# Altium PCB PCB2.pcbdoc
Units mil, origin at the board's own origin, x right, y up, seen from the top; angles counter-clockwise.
Board outline 7175 x 3700.9 mil, 2 copper layers (Top Layer, Bottom Layer); 17 components, 36 nets, 146 pads, 3 vias.
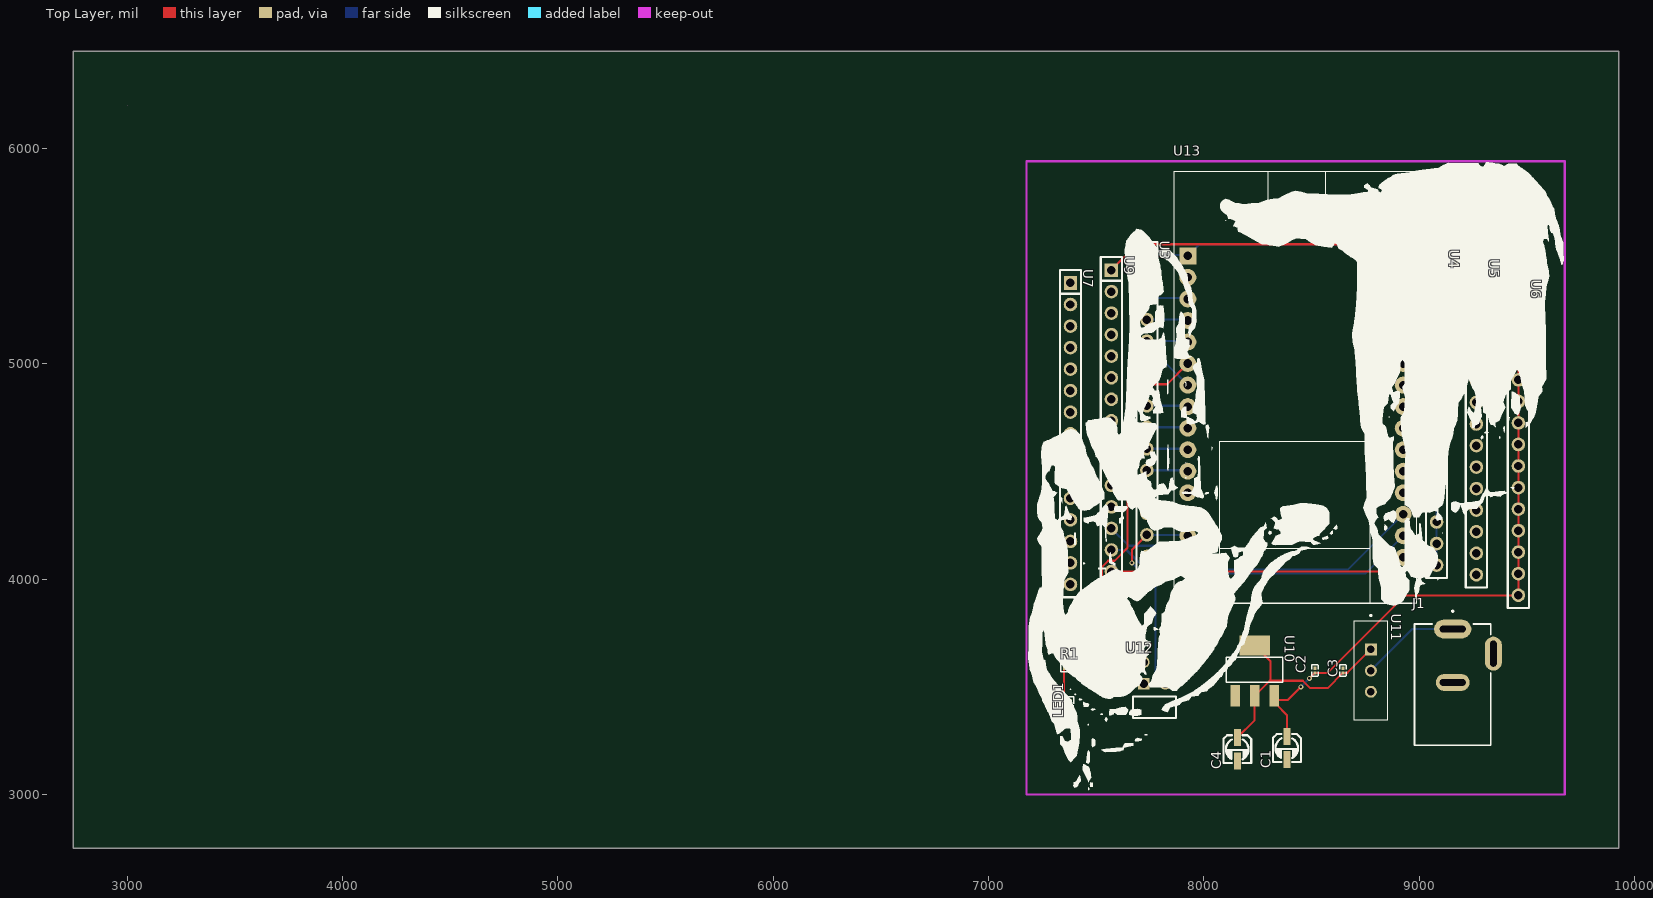
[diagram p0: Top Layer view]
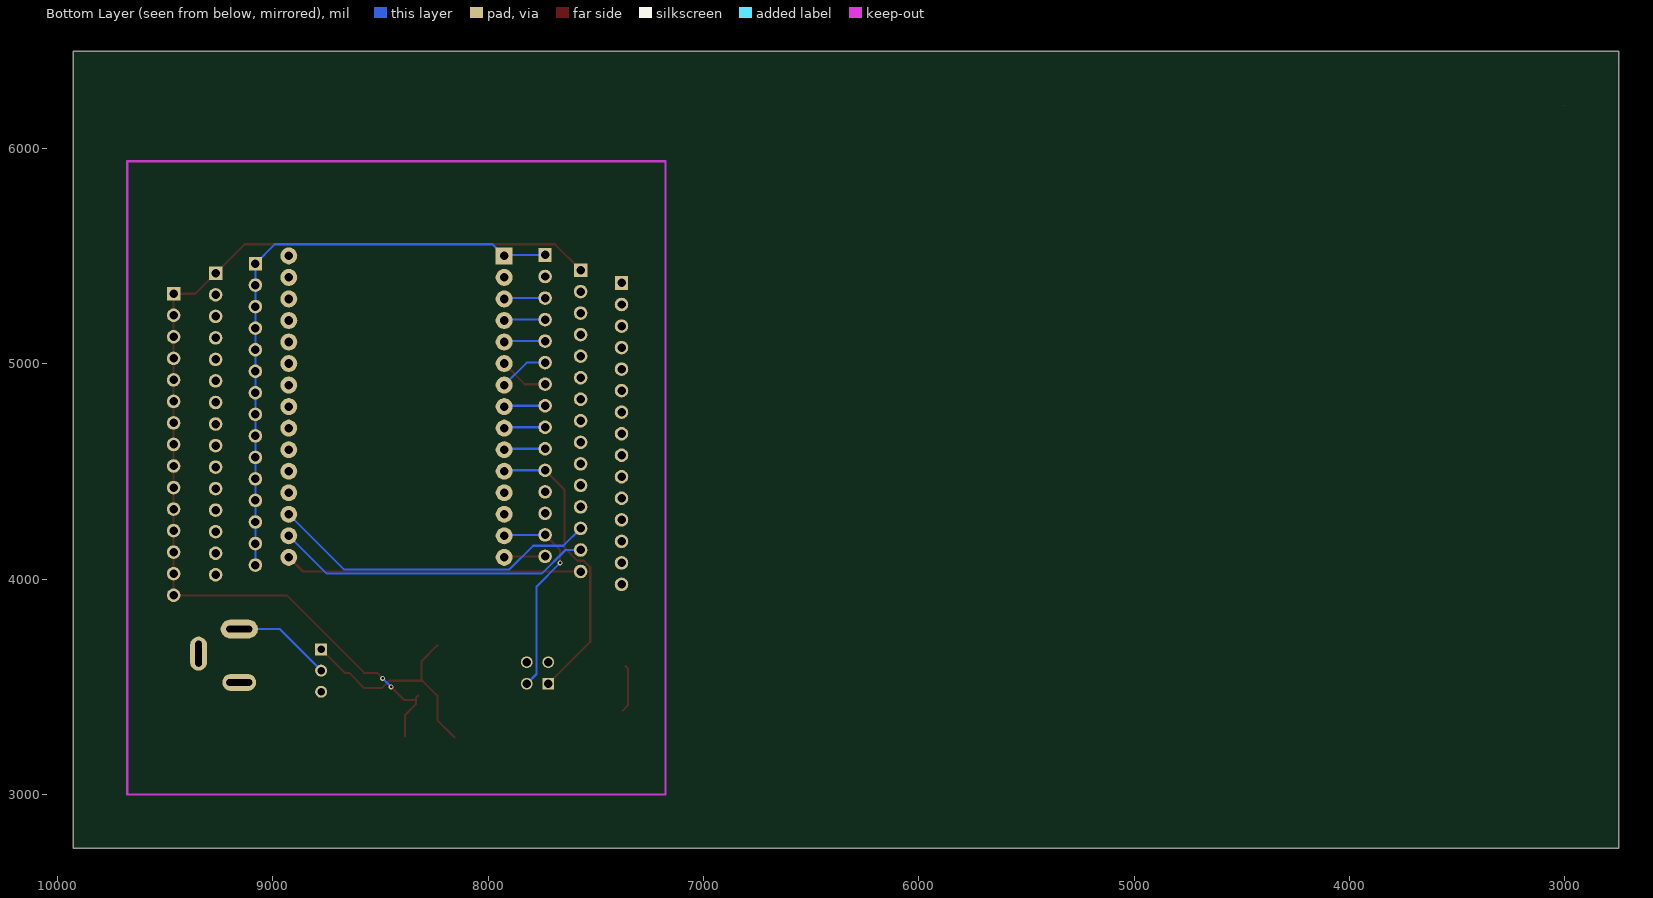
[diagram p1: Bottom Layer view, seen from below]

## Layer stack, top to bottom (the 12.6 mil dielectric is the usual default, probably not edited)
Top Layer: signal copper (thickness not stored)
Dielectric: dielectric 12.6, FR-4, Dk 4.8
Bottom Layer: signal copper (thickness not stored)

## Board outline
9925,2750 2750,2750 2750,6450.9 9925,6450.9
cut-out: 3000,6200.9 3000.1,6200.9 3000.1,6200.8 3000,6200.8

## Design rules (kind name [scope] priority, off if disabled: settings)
BoardOutlineClearance copperThickness1oz [All] p0: genericclearance=10 ignorepadtopadclearanceinfootprint=FALSE except(0: Arc-SplitContinuation Track-SplitContinuation SMDPad-SplitContinuation THPad-SplitContinuation Via-SplitContinuation Fill-SplitContinuation Poly-SplitContinuation Region-SplitContinuation Text-SplitContinuation; 6: Track-CutoutEdge SMDPad-CutoutEdge THPad-CutoutEdge Via-CutoutEdge Region-CutoutEdge; 11.8: Track-OutlineEdge SMDPad-OutlineEdge THPad-OutlineEdge Via-OutlineEdge Fill-OutlineEdge Region-OutlineEdge Poly-OutlineEdge Text-OutlineEdge Fill-CutoutEdge)
BoardOutlineClearance copperThickness2oz [All] p0: genericclearance=10 ignorepadtopadclearanceinfootprint=FALSE except(0: Arc-SplitContinuation Track-SplitContinuation SMDPad-SplitContinuation THPad-SplitContinuation Via-SplitContinuation Fill-SplitContinuation Poly-SplitContinuation Region-SplitContinuation Text-SplitContinuation; 6: Track-CutoutEdge SMDPad-CutoutEdge THPad-CutoutEdge Via-CutoutEdge Region-CutoutEdge; 11.8: Track-OutlineEdge SMDPad-OutlineEdge THPad-OutlineEdge Via-OutlineEdge Fill-OutlineEdge Region-OutlineEdge Poly-OutlineEdge Text-OutlineEdge Fill-CutoutEdge)
Clearance copperThickness1oz [(InNet('+5V') OR InNet('VCC') OR InNet('$1N3583') OR InNet('$1N3151') OR InNet('D23') OR InNet('D22') OR InNet('TX') OR InNet('RX') OR InNet('D21') OR InNet('D19') OR InNet('D18') OR InNet('D5') OR InNet('TX2') OR InNet('RX2') OR InNet('D4') OR InNet('D2') OR InNet('D15') OR InNet('3V3') OR InNet('TX0') OR InNet('RX0') OR InNet('VIN') OR InNet('D13') OR InNet('D12') OR InNet('D14') OR InNet('D27') OR InNet('D26') OR InNet('D25') OR InNet('D33') OR InNet('D32') OR InNet('D35') OR InNet('D34') OR InNet('VN') OR InNet('VP') OR InNet('EN') OR InNet('$1N3765') OR InNet('$1N3769'))] p1: gap=7 ignorepadtopadclearanceinfootprint=FALSE except(4: Track-Track; 6: Track-SMDPad SMDPad-SMDPad Track-THPad SMDPad-THPad THPad-THPad Track-Via SMDPad-Via THPad-Via Via-Via SMDPad-Fill THPad-Fill Via-Fill Fill-Fill Track-Region SMDPad-Region THPad-Region Via-Region Region-Region Track-Poly SMDPad-Poly THPad-Poly Via-Poly Fill-Poly Region-Poly Poly-Poly Track-Text SMDPad-Text THPad-Text Via-Text Fill-Text Region-Text Poly-Text Text-Text; 6.9: Track-Hole SMDPad-Hole THPad-Hole Via-Hole Fill-Hole Region-Hole Poly-Hole Text-Hole Sheet-Hole; 11.8: Track-Fill Fill-Region Track-Sheet SMDPad-Sheet THPad-Sheet Via-Sheet Fill-Sheet Region-Sheet Poly-Sheet Text-Sheet)
Clearance copperThickness2oz [All] p1: gap=7 ignorepadtopadclearanceinfootprint=FALSE except(6: Track-SMDPad SMDPad-SMDPad Track-THPad SMDPad-THPad THPad-THPad Track-Via SMDPad-Via THPad-Via Via-Via SMDPad-Fill THPad-Fill Via-Fill Fill-Fill Track-Region SMDPad-Region THPad-Region Via-Region Region-Region Track-Poly SMDPad-Poly THPad-Poly Via-Poly Fill-Poly Region-Poly Poly-Poly Track-Text SMDPad-Text THPad-Text Via-Text Fill-Text Region-Text Poly-Text Text-Text; 6.9: Track-Hole SMDPad-Hole THPad-Hole Via-Hole Fill-Hole Region-Hole Poly-Hole Text-Hole Sheet-Hole; 8: Track-Track; 11.8: Track-Fill Fill-Region Track-Sheet SMDPad-Sheet THPad-Sheet Via-Sheet Fill-Sheet Region-Sheet Poly-Sheet Text-Sheet)
DiffPairsRouting differentialPair [All] p1: maxuncoupledlength=10 minlimit=6 maxlimit=6 mostfreqgap=6 toplayer_minwidth=5 toplayer_prefwidth=10 toplayer_maxwidth=100 bottomlayer_minwidth=5 bottomlayer_prefwidth=10 bottomlayer_maxwidth=100
PasteMaskExpansion pasteMaskExpansion [All] p1: expansion=0
PlaneConnect innerPlane [All] p1: planeconnectstyle=Relief reliefexpansion=20 reliefentries=4 reliefconductorwidth=10 reliefairgap=10
PolygonConnect copperRegion [All] p1: connectstyle=Relief reliefentries=4 reliefconductorwidth=10 polygonreliefangle="90 Angle" airgapwidth=10
RoutingVias viaSize [All] p1: viastyle="Through Hole" holewidth=12.0078 minholewidth=11.811 maxholewidth=248.0314 width=24.0158 minwidth=19.685 maxwidth=393.7008
SolderMaskExpansion solderMaskExpansion [All] p1: useseparateexpansions=TRUE expansion=2 expansionbottom=2
Width copperThickness1oz [All] p1: maxlimit=100 minlimit=5 preferedwidth=10
Width copperThickness2oz [All] p1: maxlimit=100 minlimit=8 preferedwidth=10

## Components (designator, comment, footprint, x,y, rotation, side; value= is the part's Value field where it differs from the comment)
C1 "C_Ele_SMD_3x5.4mm" CAP-SMD_BD3.0-L3.3-W3.3-RD 8385,3215.9 r90 top
C2 "CAP_0201" C0201 8515,3575.9 r90 top
C3 "CAP_0201" C0201 8645,3575.9 r90 top
C4 "C_Ele_SMD_3x5.4mm" CAP-SMD_BD3.0-L3.3-W3.3-RD 8155,3210.9 r90 top
J1 "DCJ200-10-A-XX-K_REVA" GCT_DCJ200-10-A-XX-K_REVA 9155,3510.9 r0 top
LED1 "LED_0402-R" LED0402-RD_YELLOW 7375,3410.9 r90 top
R1 "Res_0603" R0603 7390,3595.9 r0 top
U3 "HX PM2.54-1x15P ZC" HDR-TH_15P-P2.54-V-F-1 7735,4805.9 r270 top
U4 "HX PM2.54-1x15P ZC" HDR-TH_15P-P2.54-V-F-1 9080,4765.9 r270 top
U5 "HX PM2.54-1x15P ZC" HDR-TH_15P-P2.54-V-F-1 9265,4720.9 r270 top
U6 "HX PM2.54-1x15P ZC" HDR-TH_15P-P2.54-V-F-1 9460,4625.9 r270 top
U7 "HX PM2.54-1x15P ZC" HDR-TH_15P-P2.54-V-F-1 7380,4675.9 r270 top
U9 "HX PM2.54-1x15P ZC" HDR-TH_15P-P2.54-V-F-1 7570,4735.9 r270 top
U10 "AMS1117-5.0(XBLW)_C18723570" SOT-223-3_L6.5-W3.4-P2.30-LS7.0-BR-1 8235,3575.9 r270 top
U11 "MINI-SPDT-SW" SW_MINI-SPDT-SW 8775,3575.9 r270 top
U12 "MTSW-102-10-L-D-472-RA" SAMTEC_MTSW-102-10-L-D-472-RA 7770,3405.9 r0 top
U13 "ESP32-DEVKIT-V1" MODULE_ESP32_DEVKIT_V1 8425,4890.9 r0 top

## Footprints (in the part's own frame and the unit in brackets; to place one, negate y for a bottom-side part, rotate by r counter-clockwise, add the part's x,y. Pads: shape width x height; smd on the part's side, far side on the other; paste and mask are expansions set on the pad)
C0201 [mil]
  rect 14.51x12.76 smd: 1(-10.8,0) 2(10.8,0)
  silkscreen extent -27,-15 27,15
CAP-SMD_BD3.0-L3.3-W3.3-RD [mm]
  rect 2x0.8 smd: 1(1.37,0) 2(-1.37,0)
  silkscreen extent -1.65,-1.64 1.65,1.66
GCT_DCJ200-10-A-XX-K_REVA [mm]
  oval 4.4x2.2 hole 0.762 slot 3.048 at 0 deg: 1(0,6.55)
  oval 4x2 hole 0.762 slot 3.048 at 0 deg: 2(0,0.25)
  oval 2x4 hole 0.762 slot 3.048 at 90 deg: 3(4.8,3.65)
  silkscreen extent -4.5,-7.15 4.5,8.75
HDR-TH_15P-P2.54-V-F-1 [mm]
  rect 1.6x1.575 hole 1: 1(-17.78,0)
  round 1.6 hole 1: 2(-15.24,0) 3(-12.7,0) 4(-10.16,0) 5(-7.62,0) 6(-5.08,0) 7(-2.54,0) 8(0,0) 9(2.54,0) 10(5.08,0) 11(7.62,0) 12(10.16,0) 13(12.7,0) 14(15.24,0) 15(17.78,0)
  silkscreen extent -19.3,-1.25 19.3,1.25
LED0402-RD_YELLOW [mm]
  rect 0.636x0.54 smd: 1(-0.538,0) 2(0.538,0)
  silkscreen extent -1.39,-0.54 1.09,0.54
MODULE_ESP32_DEVKIT_V1 [mm]
  rect 2x2 hole 1.02: 1(-12.7,15.515)
  round 2 hole 1.02: 2(-12.7,12.975) 3(-12.7,10.435) 4(-12.7,7.895) 5(-12.7,5.355) 6(-12.7,2.815) 7(-12.7,0.275) 8(-12.7,-2.265) 9(-12.7,-4.805) 10(-12.7,-7.345) 11(-12.7,-9.885) 12(-12.7,-12.425) 13(-12.7,-14.965) 14(-12.7,-17.505) 15(-12.7,-20.045) 16(12.7,-20.045) 17(12.7,-17.505) 18(12.7,-14.965) 19(12.7,-12.425) 20(12.7,-9.885) 21(12.7,-7.345) 22(12.7,-4.805) 23(12.7,-2.265) 24(12.7,0.275) 25(12.7,2.815) 26(12.7,5.355) 27(12.7,7.895) 28(12.7,10.435) 29(12.7,12.975) 30(12.7,15.515)
  silkscreen extent -14.95,-25.48 14.23,25.48
R0603 [mil]
  rect 31.75x34.02 smd: 1(-29.66,0) 2(29.66,0)
  silkscreen extent -55,-26 55,26
SAMTEC_MTSW-102-10-L-D-472-RA [mm]
  rect 1.37x1.37 hole 1.02: 01(-1.27,2.77)
  round 1.37 hole 1.02: 02(-1.27,5.31) 03(1.27,2.77) 04(1.27,5.31)
  silkscreen extent -3.29,-1.27 2.54,2.87
SOT-223-3_L6.5-W3.4-P2.30-LS7.0-BR-1 [mm]
  rect 2.5x1.1 smd: 1(2.97,-2.3) 2(2.97,0) 3(2.97,2.3)
  rect 2.34x3.6 smd: 2(-2.97,0)
  silkscreen extent -1.57,-3.33 1.37,3.33
SW_MINI-SPDT-SW [mm]
  rect 1.408x1.408 hole 0.9: 1(-2.5,0)
  round 1.408 hole 0.9: 2(0,0) 3(2.5,0)
  silkscreen extent -6.6,-2 5.8,2

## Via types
v1: diameter 24.02, hole 12.01, Top Layer to Bottom Layer, 3 vias

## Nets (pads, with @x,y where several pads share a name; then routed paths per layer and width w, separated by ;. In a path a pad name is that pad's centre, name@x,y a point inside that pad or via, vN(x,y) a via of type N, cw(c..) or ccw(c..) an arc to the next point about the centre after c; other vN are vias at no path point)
3V3: U3.1 U4.1 U4.2 U4.3 U4.4 U4.5 U4.6 U4.7 U4.8 U4.9 U4.10 U4.11 U4.12 U4.13 U4.14 U4.15 U13.1 | length 2806.4
  Bottom Layer w10: U3.1 7920.83,5505.9 U13.1 7979.17,5555.9 8990,5555.9 U4.1 U4.2 U4.3 U4.4 U4.5 U4.6 U4.7 U4.8 U4.9 U4.10 U4.11 U4.12 U4.13 U4.14 U4.15
$1N3151: LED1.1 R1.1 | length 220.5
  Top Layer w10: R1.1 7350.34,3585.9 7350.34,3414.37 LED1.1
$1N3583: J1.1 U11.2 | length 459.9
  Bottom Layer w10: U11.2 8967.87,3768.77 J1.1
$1N3765: U12.02
$1N3769: U12.04
+5V: C1.1 C2.1 U5.1 U6.1 U6.2 U6.3 U6.4 U6.5 U6.6 U6.7 U6.8 U6.9 U6.10 U6.11 U6.12 U6.13 U6.14 U6.15 U9.1 U10.3 | length 4975.1
  Top Layer w10: U9.1 7690,5555.9 9130,5555.9 U5.1 9360,5325.9 U6.1 U6.2 U6.3 U6.4 U6.5 U6.6 U6.7 U6.8 U6.9 U6.10 U6.11 U6.12 U6.13 U6.14 U6.15 9459.2,3925.1 8935,3925.1 8575,3565.1 C2.1 v1(8489.74,3539.84) ; U10.3 8335,3449.53 U10.3@8335,3439.84 ; C1.1 8385,3369.84 8335,3419.84 U10.3@8335,3439.84 ; v1(8449.74,3499.84) 8389.74,3439.84 U10.3@8335,3439.84
  Bottom Layer w10: v1(8449.74,3499.84) v1(8489.74,3539.84)
D2: U3.4 U13.4 | length 191.7
  Bottom Layer w10: U3.4 7920.83,5205.9 U13.4
D4: U3.5 U13.5 | length 191.7
  Bottom Layer w10: U3.5 7920.83,5105.9 U13.5
D5: U3.8 U13.8 | length 191.7
  Bottom Layer w10: U3.8 7920.83,4805.9 U13.8
D12: U9.4 U13.27
D13: U9.3 U13.28
D14: U9.5 U13.26
D15: U3.3 U13.3 | length 191.7
  Bottom Layer w10: U3.3 7920.83,5305.9 U13.3
D18: U3.9 U13.9 | length 191.7
  Bottom Layer w10: U3.9 7920.83,4705.9 U13.9
D19: U3.10 U13.10 | length 191.7
  Bottom Layer w10: U3.10 7920.83,4605.9 U13.10
D21: U3.11 U12.01 U13.11 | length 1368
  Top Layer w10: U12.01 7525,3709.96 7525,4055.9 7555,4085.9 7585,4085.9 7645,4145.9 7645,4415.9 U3.11
  Bottom Layer w10: U3.11 7920.83,4505.9 U13.11
D22: U3.14 U12.03 U13.14 | length 975.9
  Top Layer w10: v1(7665,4075.9) 7665,4135.9 U3.14
  Bottom Layer w10: v1(7665,4075.9) 7775,3965.9 7775,3559.96 U12.03 ; U3.14 7920.83,4205.9 U13.14
D23: U3.15 U13.15 | length 191.7
  Top Layer w10: U3.15 7920.83,4105.9 U13.15
D25: U9.8 U13.23
D26: U9.7 U13.24
D27: U9.6 U13.25
D32: U9.10 U13.21
D33: U9.9 U13.22
D34: U9.12 U13.19
D35: U9.11 U13.20
EN: U9.15 U13.16 | length 1382.3
  Top Layer w10: U9.15 8859.17,4035.9 U13.16
RX: U3.12
RX0: U13.12
RX2: U3.6 U13.7 | length 233.1
  Bottom Layer w10: U3.6 7820.83,5005.9 U13.7
TX: U3.13
TX0: U13.13
TX2: U3.7 U13.6 | length 229.7
  Top Layer w10: U3.7 7829.17,4905.9 U13.6
VCC: C3.1 C4.1 U10.2 U11.1 | length 1079.6
  Top Layer w10: C4.1 8235,3344.84 8235,3458.97 8305,3528.97 8308.88,3528.97 ; U10.2@8235,3692.82 8308.88,3618.95 8308.88,3528.97 ; U11.1 8665.77,3565.1 C3.1 8574.23,3494.33 8493.52,3494.33 8458.88,3528.97 8308.88,3528.97
VIN: U13.30
VN: U9.13 U13.18 | length 1539.7
  Bottom Layer w10: U9.13 7650,4155.9 7790,4155.9 7900,4045.9 8669.17,4045.9 U13.18
VP: U9.14 U13.17 | length 1473.4
  Bottom Layer w10: U9.14 7640,4135.9 7750,4025.9 8749.17,4025.9 U13.17
pads on no net: C1.2 C2.2 C3.2 C4.2 J1.2 J1.3 LED1.2 R1.2 U3.2 U5.2 U5.3 U5.4 U5.5 U5.6 U5.7 U5.8 U5.9 U5.10 U5.11 U5.12 U5.13 U5.14 U5.15 U7.1 U7.2 U7.3 U7.4 U7.5 U7.6 U7.7 U7.8 U7.9 U7.10 U7.11 U7.12 U7.13 U7.14 U7.15 U9.2 U10.1 U11.3 U13.2 U13.29

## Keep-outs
Board Outline Layer:
  region: 3000,6200.9 3000.1,6200.9 3000.1,6200.8 3000,6200.8
  lines w1: 3000,6200.8 3000.1,6200.8 3000.1,6200.9 3000,6200.9 3000,6200.8
  lines w10: 7175,3000 9675,3000 9675,5940.9 7175,5940.9 7175,3000

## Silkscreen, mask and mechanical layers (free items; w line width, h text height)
Top Silkscreen Layer:
  drawing of 71 lines, arcs and shapes, not listed
Mechanical Layer:
  lines w1: 3000,6200.8 3000.1,6200.8 3000.1,6200.9 3000,6200.9 3000,6200.8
